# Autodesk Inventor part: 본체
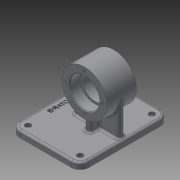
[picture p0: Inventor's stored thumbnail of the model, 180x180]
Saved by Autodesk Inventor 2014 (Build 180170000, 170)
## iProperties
Created: 2019-09
Part Number: 본체
Material: Generic
Document SubType Name: Modeling
Designer: kh
Density: 1 g/cm^3
Appearance: Default
Mass: 205.415 g
Surface Area: 495.884 cm^2
Volume: 205.415 cm^3
Author: kh
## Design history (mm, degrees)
sketch "Sketch1"
  geometry: L1 (49, -63)-(-49, -63); L2 (-49, -63)-(-49, 63); L3 (-49, 63)-(49, 63); L4 (49, 63)-(49, -63); L5 (49, -63)-(-49, 63); L6 (-49, -63)-(49, 63); 1 further point
  constraints: 12 end point, 2 midpoint, 2 parallel, 1 horizontal, 1 perpendicular
  dimensions: "d0" = 98 distance of L2.end L3.end; "d1" = 126 distance of L1.end L2.end
extrude "Extrusion1" new body sketch "Sketch1" distance "d2" = 9; taper "d3" = 0 deg
workplane "Work Plane1"
sketch "Sketch2"
  geometry: L1 (-59, 42)-(-59, 84); L2 (0, 126)-(0, 0) reference; L3 (-59, 42)-(-91, 42); L4 (-91, 42)-(-91, 84); L5 (-91, 84)-(-59, 84); L6 (-91, 63)-(-59, 63); L7 (0, 126)-(-9, 126) reference; L8 (-80, 42)-(-80, 57); L9 (-80, 57)-(-77, 57); L10 (-77, 57)-(-77, 69); L11 (-77, 69)-(-80, 69); L12 (-80, 69)-(-80, 84); 1 further point
  constraints: 20 end point, 6 perpendicular, 2 midpoint, 2 parallel, 2 point on line, 1 vertical
  dimensions: "d5" = 59 distance between parallel lines of L2 L1; "d6" = 42 distance of L3.end L4.end; "d7" = 63 distance between parallel lines of L7 L6; "d8" = 64 diameter of L4 L1; "d9" = 42 diameter of L8 L1; "d10" = 36 diameter of L10 L1; "d11" = 42 diameter of L12 L1; "d12" = 15 distance of L8.start L8.end; "d13" = 15 distance of L11.end L12.end
revolve "Revolution1" sketch "Sketch2" stored, may be unused: angle "d14" = 90 deg
sketch "Sketch3"
  geometry: L1 (-49, 63)-(49, 63) reference; L2 (-49, -63)-(-49, 63) reference; L3 (-19, 4)-(45, 4); L4 (45, 4)-(45, -4); L5 (45, -4)-(-19, -4); L6 (-19, -4)-(-19, 4); L7 (-19, 4)-(45, -4); L8 (45, 4)-(-19, -4); L9 (17, 17)-(9, 17); L10 (9, 17)-(9, -17); L11 (9, -17)-(17, -17); L12 (17, -17)-(17, 17); L13 (17, 17)-(9, -17); L14 (9, 17)-(17, -17); 2 further points
  constraints: 24 end point, 4 midpoint, 4 parallel, 2 horizontal, 2 perpendicular
  dimensions: "d15" = 63 distance from line of L1 point (13, 0); "d16" = 62 distance from line of L2 point (13, 0); "d17" = 64 distance of L4.end L5.end; "d18" = 8 distance of L5.end L3.start; "d19" = 8 distance of L11.end L10.end; "d20" = 34 distance of L10.end L9.end
extrude "Extrusion2" join sketch "Sketch3" stored distance "d21" = 9; taper "d22" = 0 deg
fillet "Fillet1" dims "d23" = 12
fillet "Fillet2" dims "d24" = 3
fillet "Fillet3" dims "d25" = 3
fillet "Fillet4" dims "d26" = 3
chamfer "Chamfer1" distance "d27" = 1; stored, may be unused: second distance "d28" = 2, angle "d29" = 45 deg
fillet "Fillet5" dims "d30" = 0.3
sketch "Sketch4"
  geometry: C1 r 32 at (0, 0) reference; 2 further points
  constraints: 1 vertical alignment
  dimensions: "d31" = 26 distance of C1.centre point (0, 26)
hole "Hole1" sketch "Sketch4" at (0, 26) diameter "d32" = 3.242; stored, may be unused: countersink angle "d36" = 90 deg, drill point angle "d38" = 118 deg; dims "d33" = 8, "d34" = 4, "d35" = 2, "d37" = 10
pattern_circular "Circular Pattern1" dims angle "d40" = 360 deg
mirror "Mirror1"
hole "Hole2" diameter "d44" = 4.5; stored, may be unused: countersink angle "d48" = 90 deg, drill point angle "d50" = 118 deg; dims "d42" = 10, "d43" = 10, "d45" = 8, "d46" = 8, "d47" = 4.4, "d49" = 10
pattern_linear "Rectangular Pattern1" dims "d53" = 102, "d56" = 74
sketch "Sketch5"
  geometry: L1 (-42.002, -20.739)-(-42.002, 20.739); L2 (-42.002, 20.739)-(-35.998, 20.739); L3 (-35.998, 20.739)-(-35.998, -20.739); L4 (-35.998, -20.739)-(-42.002, -20.739); L5 (-42.002, -20.739)-(-35.998, 20.739); L6 (37, 63)-(-37, 63) reference; L7 (-49, 51)-(-49, -51) reference; 2 further points
  constraints: 2 end point, 1 midpoint, 2 other
  dimensions: "d57" = 63 distance from line of L6 point (-39, 0); "d58" = 10 distance from line of point (-39, 0) L7
emboss "Emboss1" sketch "Sketch5" dims "d5" = 59, "d6" = 42, "d7" = 63, "d8" = 64, "d9" = 42, "d10" = 36, "d11" = 42, "d12" = 15, "d13" = 15, "d59" = 0.5, "d60" = 0
body "Solid1"
other parameters: "d4" = -36
